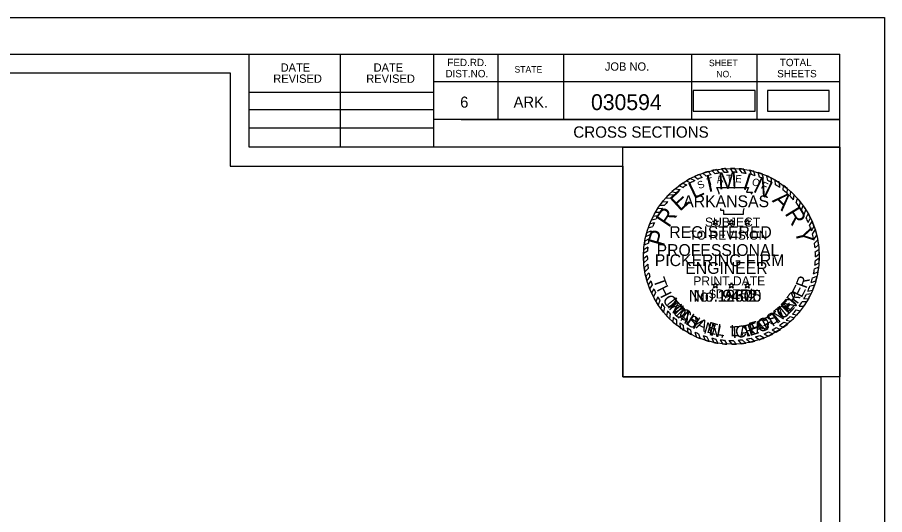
# Model space of a CAD drawing. Extents: x 1368713 to 1370673, y 380279 to 380950.
# Drawn here: x 1370223.2 to 1370315.2, y 380471.1 to 380523.8 of the extents above; entities that cross this region are included whole.
import ezdxf

# ---------------------------------------------------------------- set-up
doc = ezdxf.new("R2010")
doc.units = 0
for name, color, linetype in [('R_Border', 7, 'Continuous'), ('R_Border Notes', 7, 'Continuous'), ('R_No Plot', 7, 'Continuous'), ('R_Water', 7, 'Continuous'), ('STAMP_PE_CRAFTON', 7, 'Continuous'), ('STAMP_PE_FOSTER', 7, 'Continuous'), ('STAMP_PE_SEAL-INFO', 7, 'Continuous'), ('STAMP_PE_TAEGTMEYER', 7, 'Continuous'), ('STAMP_PE_TXT', 7, 'Continuous'), ('STAMP_PRELIMINARY', 7, 'Continuous')]:
    doc.layers.add(name, color=color, linetype=linetype)

msp = doc.modelspace()

# ---------------------------------------------------------------- linework, layer by layer
at = {"layer": 'R_Border'}
for p, q in [((1369994.283, 380519.876), (1370310.463, 380519.876)), ((1370247.823, 380509.996), (1370247.823, 380519.876)), ((1370257.503, 380509.996), (1370257.503, 380519.876)), ((1370267.363, 380519.876), (1370267.363, 380509.996)), ((1370274.203, 380519.876), (1370274.203, 380512.936)), ((1370281.143, 380519.876), (1370281.143, 380512.936)), ((1370294.723, 380519.876), (1370294.723, 380512.936)), ((1370301.663, 380519.876), (1370301.663, 380512.936)), ((1370310.463, 380314.416), (1370310.463, 380519.876)), ((1370310.463, 380516.936), (1370267.363, 380516.936)), ((1370310.463, 380516.956), (1370310.463, 380516.956)), ((1370247.823, 380515.856), (1370267.363, 380515.856)), ((1370247.823, 380513.996), (1370267.363, 380513.996)), ((1370310.463, 380512.936), (1370267.363, 380512.936)), ((1370270.323, 380512.936), (1370310.463, 380512.936)), ((1370247.823, 380512.056), (1370267.363, 380512.056)), ((1370310.463, 380509.996), (1370247.823, 380509.996))]:
    msp.add_line(p, q, dxfattribs=at)
at = {"layer": 'R_No Plot'}
for points in [[(1369981.875, 380523.77), (1370315.215, 380523.77), (1370315.215, 380310.433), (1369981.875, 380310.433)], [(1370308.463, 380419.146), (1369996.283, 380419.146), (1369996.283, 380517.876), (1370245.823, 380517.876), (1370245.823, 380507.996), (1370263.363, 380507.996), (1370287.463, 380507.996), (1370287.463, 380485.663), (1370308.463, 380485.663)], [(1369996.283, 380517.876), (1370245.823, 380517.876), (1370245.823, 380507.996), (1370263.363, 380507.996), (1370287.463, 380507.996), (1370287.463, 380485.663), (1370308.463, 380485.663), (1370308.463, 380316.416), (1369996.283, 380316.416)], [(1370287.463, 380509.996), (1370310.463, 380509.996), (1370310.463, 380485.663), (1370287.463, 380485.663)]]:
    msp.add_lwpolyline(points, close=True, dxfattribs=at)
at = {"layer": 'R_Water'}
for points in [[(1370294.911, 380513.843), (1370301.474, 380513.843), (1370301.474, 380516.029), (1370294.911, 380516.029)], [(1370302.781, 380513.843), (1370309.344, 380513.843), (1370309.344, 380516.029), (1370302.781, 380516.029)]]:
    msp.add_lwpolyline(points, close=True, dxfattribs=at)
at = {"layer": 'STAMP_PE_SEAL-INFO'}
for p, q in [((1370295.922, 380507.251), (1370296.303, 380506.946)), ((1370296.513, 380507.433), (1370296.801, 380507.086)), ((1370296.901, 380507.53), (1370297.257, 380507.187)), ((1370297.383, 380507.626), (1370297.682, 380507.259)), ((1370297.899, 380507.7), (1370298.18, 380507.317)), ((1370298.634, 380507.346), (1370298.322, 380507.739)), ((1370299.132, 380507.35), (1370298.854, 380507.76)), ((1370299.59, 380507.33), (1370299.332, 380507.754)), ((1370300.096, 380507.279), (1370299.804, 380507.723)), ((1370300.522, 380507.214), (1370300.264, 380507.67)), ((1370301.084, 380507.096), (1370300.91, 380507.555)), ((1370301.486, 380506.987), (1370301.326, 380507.456)), ((1370301.937, 380506.841), (1370301.796, 380507.32)), ((1370302.356, 380506.681), (1370302.211, 380507.177)), ((1370294.188, 380506.445), (1370294.62, 380506.222)), ((1370294.636, 380506.696), (1370295.099, 380506.471)), ((1370295.067, 380506.908), (1370295.456, 380506.633)), ((1370295.574, 380507.123), (1370295.869, 380506.798)), ((1370302.817, 380506.475), (1370302.714, 380506.973)), ((1370303.263, 380506.246), (1370303.176, 380506.755)), ((1370303.65, 380506.019), (1370303.611, 380506.52)), ((1370304.085, 380505.733), (1370304.054, 380506.248)), ((1370292.66, 380505.307), (1370293.119, 380505.169)), ((1370293.004, 380505.608), (1370293.533, 380505.507)), ((1370293.38, 380505.935), (1370293.836, 380505.73)), ((1370293.801, 380506.201), (1370294.243, 380505.999)), ((1370297.436, 380505.73), (1370300.78, 380505.73)), ((1370297.557, 380505.422), (1370297.436, 380505.73)), ((1370297.661, 380505.124), (1370297.557, 380505.422)), ((1370300.78, 380505.73), (1370300.555, 380505.238)), ((1370304.446, 380505.466), (1370304.48, 380505.953)), ((1370304.892, 380505.094), (1370304.912, 380505.616)), ((1370305.205, 380504.801), (1370305.274, 380505.3)), ((1370292.002, 380504.64), (1370292.523, 380504.601)), ((1370292.324, 380504.984), (1370292.869, 380504.943)), ((1370297.668, 380505.01), (1370297.661, 380505.124)), ((1370300.555, 380505.238), (1370301.187, 380505.238)), ((1370301.187, 380505.238), (1370301.042, 380505.01)), ((1370305.564, 380504.428), (1370305.63, 380504.954)), ((1370305.837, 380504.112), (1370305.974, 380504.583)), ((1370291.143, 380503.515), (1370291.659, 380503.548)), ((1370291.378, 380503.859), (1370291.883, 380503.854)), ((1370291.656, 380504.228), (1370292.205, 380504.251)), ((1370297.859, 380503.301), (1370297.833, 380503.519)), ((1370300.297, 380503.519), (1370300.219, 380503.209)), ((1370306.161, 380503.694), (1370306.297, 380504.194)), ((1370306.381, 380503.379), (1370306.559, 380503.843)), ((1370290.666, 380502.69), (1370291.164, 380502.755)), ((1370290.897, 380503.114), (1370291.386, 380503.134)), ((1370298.174, 380503.301), (1370297.859, 380503.301)), ((1370298.174, 380502.871), (1370298.174, 380503.301)), ((1370300.203, 380502.871), (1370298.174, 380502.871)), ((1370300.219, 380503.209), (1370300.203, 380502.871)), ((1370306.689, 380502.882), (1370306.872, 380503.373)), ((1370306.889, 380502.515), (1370307.115, 380502.96)), ((1370290.294, 380501.869), (1370290.798, 380502.015)), ((1370290.478, 380502.301), (1370290.981, 380502.405)), ((1370307.12, 380502.031), (1370307.346, 380502.516)), ((1370307.26, 380501.694), (1370307.524, 380502.128)), ((1370307.455, 380501.145), (1370307.726, 380501.62)), ((1370289.883, 380500.552), (1370290.353, 380500.745)), ((1370289.987, 380500.96), (1370290.465, 380501.128)), ((1370290.144, 380501.463), (1370290.628, 380501.599)), ((1370307.563, 380500.781), (1370307.857, 380501.233)), ((1370290.161, 380499.847), (1370289.716, 380499.625)), ((1370290.247, 380500.306), (1370289.782, 380500.057)), ((1370307.696, 380500.222), (1370308.015, 380500.669)), ((1370307.765, 380499.842), (1370308.118, 380500.195)), ((1370290.066, 380498.986), (1370289.645, 380498.73)), ((1370290.102, 380499.412), (1370289.666, 380499.131)), ((1370307.831, 380499.333), (1370308.204, 380499.669)), ((1370307.863, 380498.915), (1370308.254, 380499.206)), ((1370290.049, 380498.493), (1370289.644, 380498.158)), ((1370290.056, 380498.086), (1370289.665, 380497.761)), ((1370307.865, 380497.991), (1370308.284, 380498.268)), ((1370307.876, 380498.397), (1370308.281, 380498.718)), ((1370290.089, 380497.591), (1370289.718, 380497.234)), ((1370290.141, 380497.162), (1370289.787, 380496.788)), ((1370307.775, 380497.097), (1370308.218, 380497.316)), ((1370307.825, 380497.485), (1370308.259, 380497.742)), ((1370290.22, 380496.703), (1370289.88, 380496.335)), ((1370290.313, 380496.284), (1370290.001, 380495.869)), ((1370307.576, 380496.145), (1370308.048, 380496.347)), ((1370307.684, 380496.597), (1370308.139, 380496.792)), ((1370290.437, 380495.837), (1370290.142, 380495.419)), ((1370290.578, 380495.414), (1370290.296, 380495.002)), ((1370307.294, 380495.271), (1370307.777, 380495.402)), ((1370307.429, 380495.651), (1370307.919, 380495.852)), ((1370290.744, 380494.987), (1370290.483, 380494.565)), ((1370290.916, 380494.604), (1370290.688, 380494.143)), ((1370306.919, 380494.42), (1370307.407, 380494.488)), ((1370307.08, 380494.757), (1370307.568, 380494.853)), ((1370291.151, 380494.146), (1370290.96, 380493.656)), ((1370291.387, 380493.742), (1370291.203, 380493.271)), ((1370291.589, 380493.43), (1370291.479, 380492.878)), ((1370306.475, 380493.641), (1370306.953, 380493.635)), ((1370306.647, 380493.922), (1370307.148, 380493.976)), ((1370291.87, 380493.04), (1370291.768, 380492.509)), ((1370292.174, 380492.662), (1370292.087, 380492.142)), ((1370305.828, 380492.753), (1370306.289, 380492.674)), ((1370306.136, 380493.147), (1370306.64, 380493.15)), ((1370292.476, 380492.325), (1370292.414, 380491.802)), ((1370292.799, 380491.999), (1370292.769, 380491.47)), ((1370293.143, 380491.687), (1370293.14, 380491.158)), ((1370304.784, 380491.688), (1370305.255, 380491.559)), ((1370305.19, 380492.061), (1370305.631, 380491.923)), ((1370305.445, 380492.32), (1370305.922, 380492.235)), ((1370293.503, 380491.392), (1370293.522, 380490.868)), ((1370293.842, 380491.143), (1370293.878, 380490.624)), ((1370294.269, 380490.861), (1370294.329, 380490.348)), ((1370294.619, 380490.655), (1370294.71, 380490.142)), ((1370303.294, 380490.648), (1370303.711, 380490.416)), ((1370303.709, 380490.893), (1370304.158, 380490.698)), ((1370304.053, 380491.121), (1370304.491, 380490.932)), ((1370304.513, 380491.464), (1370304.981, 380491.318)), ((1370295.1, 380490.405), (1370295.257, 380489.884)), ((1370295.473, 380490.236), (1370295.645, 380489.726)), ((1370295.965, 380490.044), (1370296.174, 380489.542)), ((1370296.375, 380489.909), (1370296.601, 380489.42)), ((1370296.883, 380489.771), (1370297.095, 380489.305)), ((1370297.28, 380489.685), (1370297.527, 380489.227)), ((1370300.563, 380489.67), (1370300.952, 380489.33)), ((1370301.056, 380489.774), (1370301.434, 380489.449)), ((1370301.515, 380489.898), (1370301.932, 380489.601)), ((1370302.008, 380490.061), (1370302.451, 380489.793)), ((1370302.427, 380490.226), (1370302.851, 380489.965)), ((1370302.887, 380490.435), (1370303.37, 380490.223)), ((1370297.78, 380489.603), (1370298.02, 380489.163)), ((1370298.217, 380489.556), (1370298.491, 380489.127)), ((1370298.702, 380489.529), (1370299.004, 380489.116)), ((1370299.161, 380489.527), (1370299.505, 380489.131)), ((1370299.68, 380489.554), (1370300.006, 380489.174)), ((1370300.118, 380489.6), (1370300.491, 380489.242))]:
    msp.add_line(p, q, dxfattribs=at)
for radius, start, end in [(9.323, 105.23389, 109.03519), (9.323, 99.75254, 102.77648), (8.914, 98.25799, 101.03289), (9.323, 93.93815, 96.55172), (8.914, 92.11016, 95.03666), (9.323, 87.72979, 90.67067), (8.914, 85.96279, 88.9097), (9.323, 81.97315, 84.82355), (8.914, 79.92642, 82.69597), (9.323, 75.31251, 77.94263), (9.323, 69.60611, 72.30577), (9.323, 117.65441, 120.80988), (8.914, 115.68692, 119.15827), (9.323, 111.31242, 114.70259), (8.914, 110.30864, 113.16588), (8.914, 104.03521, 107.36155), (8.914, 73.55748, 76.23144), (8.914, 67.62483, 70.50398), (9.323, 63.13288, 66.2704), (8.914, 61.15575, 64.37837), (9.323, 56.90029, 60.09423), (9.323, 129.73259, 132.53764), (8.914, 127.52969, 130.96829), (9.323, 123.61993, 126.59063), (8.914, 121.97456, 125.11001), (8.914, 54.92383, 58.27016), (8.914, 48.30163, 52.03953), (9.323, 50.3492, 53.71593), (9.323, 44.3405, 47.39292), (9.323, 135.40208, 138.30314), (8.914, 133.13306, 136.25623), (8.914, 42.22116, 45.55119), (9.323, 38.12472, 41.23157), (9.323, 147.00719, 149.89904), (9.323, 141.60556, 144.44865), (8.914, 145.01972, 148.21036), (8.914, 139.30101, 142.58729), (8.914, 36.13503, 39.53106), (9.323, 31.96138, 35.42937), (9.323, 152.86398, 155.51889), (8.914, 151.03153, 153.57304), (8.914, 29.90321, 33.66454), (9.323, 25.93909, 29.01247), (9.323, 158.40766, 161.07015), (8.914, 156.34018, 159.23194), (8.914, 23.77322, 27.22114), (8.914, 17.68022, 21.42509), (9.323, 19.95381, 23.31409), (9.323, 164.3068, 166.89395), (8.914, 162.43309, 165.00133), (8.914, 11.54445, 15.23639), (9.323, 13.84205, 17.44468), (9.323, 170.0003, 172.68778), (8.914, 167.90481, 170.90393), (8.914, 5.7599, 9.06056), (9.323, 7.58519, 10.86211), (9.323, 175.74093, 178.2066), (8.914, 173.73, 176.47337), (8.914, 359.73289, 3.06392), (9.323, 1.72155, 4.72681), (9.323, 181.72508, 184.16255), (8.914, 179.64537, 182.26333), (8.914, 353.86319, 357.12742), (9.323, 355.71562, 358.95694), (9.323, 187.42037, 190.19271), (8.914, 185.45389, 188.23401), (8.914, 348.07782, 351.34355), (9.323, 349.83047, 353.08845), (9.323, 193.03695, 195.99732), (8.914, 191.22736, 193.98583), (8.914, 341.77699, 345.09248), (9.323, 343.89247, 347.03502), (9.323, 198.89671, 201.62812), (8.914, 196.96751, 199.83526), (8.914, 335.6038, 339.18578), (9.323, 337.38367, 340.99332), (9.323, 204.54793, 207.43282), (8.914, 202.77613, 205.47915), (8.914, 329.55488, 333.20757), (9.323, 331.40371, 334.93315), (9.323, 210.86355, 213.65709), (8.914, 208.78826, 211.79343), (8.914, 214.18375, 217.27474), (8.914, 323.58513, 327.44069), (9.323, 325.44052, 328.98725), (9.323, 216.61154, 219.49098), (8.914, 220.39088, 223.30564), (8.914, 316.65308, 320.37109), (9.323, 318.28455, 321.80429), (9.323, 222.47995, 225.38008), (8.914, 226.24938, 229.24068), (8.914, 310.77436, 314.31605), (9.323, 312.45177, 315.66328), (9.323, 228.36648, 231.34802), (8.914, 232.22904, 234.93361), (9.323, 234.29502, 236.94517), (8.914, 238.22227, 240.83529), (8.914, 299.07679, 302.17235), (9.323, 300.62101, 303.87026), (8.914, 304.82299, 308.51428), (9.323, 306.37206, 310.20799), (9.323, 240.1977, 242.86128), (8.914, 244.32043, 246.94859), (9.323, 246.57598, 249.15579), (8.914, 250.34912, 253.12157), (8.914, 256.50505, 259.11916), (8.914, 280.34588, 283.58137), (8.914, 286.64233, 289.97826), (9.323, 288.57086, 291.97334), (8.914, 292.87452, 296.11851), (9.323, 294.64808, 298.21662), (9.323, 252.59667, 255.32518), (9.323, 258.44328, 261.13983), (8.914, 262.37828, 265.20115), (9.323, 264.19784, 267.10092), (8.914, 268.3215, 271.27698), (9.323, 270.25484, 273.33609), (8.914, 274.61565, 277.44863), (9.323, 276.42389, 279.43574), (9.323, 282.31994, 285.37019)]:
    msp.add_arc((1370298.963, 380498.438), radius, start, end, dxfattribs=at)
at = {"layer": 'STAMP_PE_TXT'}
for p, q in [((1370297.142, 380502.01), (1370296.944, 380502.154)), ((1370296.944, 380502.154), (1370297.189, 380502.154)), ((1370297.066, 380501.776), (1370297.142, 380502.01)), ((1370297.265, 380501.921), (1370297.066, 380501.776)), ((1370297.189, 380502.154), (1370297.265, 380502.387)), ((1370297.265, 380502.387), (1370297.34, 380502.154)), ((1370297.463, 380501.776), (1370297.265, 380501.921)), ((1370297.34, 380502.154), (1370297.586, 380502.154)), ((1370297.586, 380502.154), (1370297.387, 380502.01)), ((1370297.387, 380502.01), (1370297.463, 380501.776)), ((1370298.84, 380502.01), (1370298.642, 380502.154)), ((1370298.642, 380502.154), (1370298.887, 380502.154)), ((1370298.764, 380501.776), (1370298.84, 380502.01)), ((1370298.963, 380501.921), (1370298.764, 380501.776)), ((1370298.887, 380502.154), (1370298.963, 380502.387)), ((1370298.963, 380502.387), (1370299.038, 380502.154)), ((1370299.161, 380501.776), (1370298.963, 380501.921)), ((1370299.038, 380502.154), (1370299.284, 380502.154)), ((1370299.284, 380502.154), (1370299.085, 380502.01)), ((1370299.085, 380502.01), (1370299.161, 380501.776)), ((1370300.538, 380502.01), (1370300.34, 380502.154)), ((1370300.34, 380502.154), (1370300.585, 380502.154)), ((1370300.462, 380501.776), (1370300.538, 380502.01)), ((1370300.661, 380501.921), (1370300.462, 380501.776)), ((1370300.585, 380502.154), (1370300.661, 380502.387)), ((1370300.661, 380502.387), (1370300.736, 380502.154)), ((1370300.859, 380501.776), (1370300.661, 380501.921)), ((1370300.736, 380502.154), (1370300.982, 380502.154)), ((1370300.982, 380502.154), (1370300.783, 380502.01)), ((1370300.783, 380502.01), (1370300.859, 380501.776)), ((1370297.142, 380495.303), (1370296.944, 380495.447)), ((1370296.944, 380495.447), (1370297.189, 380495.447)), ((1370297.066, 380495.069), (1370297.142, 380495.303)), ((1370297.265, 380495.214), (1370297.066, 380495.069)), ((1370297.189, 380495.447), (1370297.265, 380495.68)), ((1370297.265, 380495.68), (1370297.34, 380495.447)), ((1370297.463, 380495.069), (1370297.265, 380495.214)), ((1370297.34, 380495.447), (1370297.586, 380495.447)), ((1370297.586, 380495.447), (1370297.387, 380495.303)), ((1370297.387, 380495.303), (1370297.463, 380495.069)), ((1370298.84, 380495.303), (1370298.642, 380495.447)), ((1370298.642, 380495.447), (1370298.887, 380495.447)), ((1370298.764, 380495.069), (1370298.84, 380495.303)), ((1370298.963, 380495.214), (1370298.764, 380495.069)), ((1370298.887, 380495.447), (1370298.963, 380495.68)), ((1370298.963, 380495.68), (1370299.038, 380495.447)), ((1370299.161, 380495.069), (1370298.963, 380495.214)), ((1370299.038, 380495.447), (1370299.284, 380495.447)), ((1370299.284, 380495.447), (1370299.085, 380495.303)), ((1370299.085, 380495.303), (1370299.161, 380495.069)), ((1370300.538, 380495.303), (1370300.34, 380495.447)), ((1370300.34, 380495.447), (1370300.585, 380495.447)), ((1370300.462, 380495.069), (1370300.538, 380495.303)), ((1370300.661, 380495.214), (1370300.462, 380495.069)), ((1370300.585, 380495.447), (1370300.661, 380495.68)), ((1370300.661, 380495.68), (1370300.736, 380495.447)), ((1370300.859, 380495.069), (1370300.661, 380495.214)), ((1370300.736, 380495.447), (1370300.982, 380495.447)), ((1370300.982, 380495.447), (1370300.783, 380495.303)), ((1370300.783, 380495.303), (1370300.859, 380495.069))]:
    msp.add_line(p, q, dxfattribs=at)
at = {"layer": 'STAMP_PRELIMINARY'}
msp.add_circle((1370298.963, 380498.438), 9.323, dxfattribs=at)

# ---------------------------------------------------------------- texts
at = {"layer": 'R_Border'}
for s, height, p in [('FED.RD.', 0.7819, (1370268.843, 380518.596)), ('SHEET', 0.684, (1370296.583, 380518.596)), ('TOTAL', 0.7819, (1370304.103, 380518.596)), ('DATE', 0.8792, (1370251.16, 380518.012)), ('DATE', 0.8792, (1370261.02, 380518.012)), ('DIST.NO.', 0.7819, (1370268.643, 380517.416)), ('STATE', 0.684, (1370275.963, 380517.916)), ('JOB NO.', 0.8792, (1370285.543, 380518.116)), ('SHEETS', 0.7819, (1370303.823, 380517.416)), ('REVISED', 0.8792, (1370250.38, 380516.832)), ('REVISED', 0.8792, (1370260.24, 380516.832)), ('NO.', 0.684, (1370297.363, 380517.416)), ('6', 1.172, (1370270.203, 380514.196)), ('ARK.', 1.1723, (1370275.863, 380514.196))]:
    msp.add_text(s, height=height, rotation=360, dxfattribs=at).set_placement(p)
at = {"layer": 'R_Border Notes'}
for s, height, p in [('030594', 1.68, (1370284.074, 380513.941)), ('CROSS SECTIONS', 1.2, (1370282.201, 380511.014))]:
    msp.add_text(s, height=height, rotation=360, dxfattribs=at).set_placement(p)
at = {"layer": 'STAMP_PE_CRAFTON'}
for s, rotation, p in [('No. 12370', 360, (1370294.425, 380493.635)), ('T', 310.74416, (1370291.929, 380493.336)), ('N', 49.24107, (1370305.245, 380492.46)), ('O', 317.64216, (1370292.596, 380492.525)), ('N', 324.45371, (1370293.442, 380491.74)), ('T', 34.11362, (1370303.539, 380491.077)), ('O', 41.83906, (1370304.398, 380491.679)), ('Y', 331.16864, (1370294.475, 380491.024)), ('A', 20.51248, (1370301.643, 380490.194)), ('F', 28.78207, (1370302.624, 380490.568)), ('N', 347.47515, (1370296.529, 380490.108)), ('C', 6.01169, (1370299.434, 380489.779)), ('R', 14.81888, (1370300.53, 380489.894)), ('.', 356.89262, (1370297.759, 380489.831))]:
    msp.add_text(s, height=1.25, rotation=rotation, dxfattribs=at).set_placement(p)
at = {"layer": 'STAMP_PE_FOSTER'}
for s, height, rotation, p in [('No. 9402', 1.25, 360, (1370294.948, 380493.635)), ('R', 1.2, 54.5031, (1370305.687, 380493.249)), ('M', 1.2, 308.33902, (1370292.079, 380493.46)), ('E', 1.2, 46.96131, (1370304.963, 380492.428)), ('I', 1.2, 314.18423, (1370292.876, 380492.523)), ('C', 1.2, 319.87327, (1370293.23, 380492.169)), ('S', 1.2, 31.72336, (1370303.153, 380491.051)), ('T', 1.2, 39.41938, (1370304.105, 380491.678)), ('H', 1.2, 327.72349, (1370294.16, 380491.433)), ('A', 1.2, 335.72761, (1370295.14, 380490.851)), ('F', 1.2, 15.86908, (1370300.998, 380490.193)), ('O', 1.2, 23.71897, (1370302.042, 380490.521)), ('E', 1.2, 343.5779, (1370296.278, 380490.381)), ('L', 1.2, 350.81148, (1370297.337, 380490.103)), ('L', 1.2, 1.26658, (1370298.876, 380489.947)), ('.', 1.2, 6.80354, (1370299.923, 380490.005))]:
    msp.add_text(s, height=height, rotation=rotation, dxfattribs=at).set_placement(p)
at = {"layer": 'STAMP_PE_TAEGTMEYER'}
for s, rotation, p in [('T', 289.64597, (1370290.657, 380495.948)), ('R', 69.57001, (1370306.908, 380494.953)), ('H', 296.73386, (1370291.017, 380494.964)), ('E', 63.0984, (1370306.409, 380493.971)), ('O', 303.77078, (1370291.61, 380493.856)), ('No. 19605', 360, (1370294.425, 380493.635)), ('Y', 53.99864, (1370305.74, 380493.031)), ('M', 314.20329, (1370292.265, 380492.905)), ('E', 46.80938, (1370305.001, 380492.216)), ('A', 321.0594, (1370293.226, 380491.94)), ('M', 39.30005, (1370303.961, 380491.336)), ('S', 327.82385, (1370294.053, 380491.296)), ('G', 23.30524, (1370301.962, 380490.3)), ('T', 31.46601, (1370303.063, 380490.793)), ('N', 344.27273, (1370295.949, 380490.29)), ('T', 3.00609, (1370298.827, 380489.759)), ('A', 8.98261, (1370299.874, 380489.814)), ('E', 17.68363, (1370300.913, 380489.97)), ('.', 350.64643, (1370297.162, 380489.958))]:
    msp.add_text(s, height=1.25, rotation=rotation, dxfattribs=at).set_placement(p)
at = {"layer": 'STAMP_PE_TXT'}
for s, height, rotation, p in [('S', 0.781, 23.5541, (1370295.561, 380505.542)), ('T', 0.781, 16.311, (1370296.484, 380505.914)), ('A', 0.781, 9.0679, (1370297.447, 380506.167)), ('T', 0.781, 1.82479, (1370298.433, 380506.296)), ('E', 0.781, 355.20019, (1370299.343, 380506.305)), ('O', 0.781, 342.25065, (1370301.07, 380506.028)), ('F', 0.781, 335.00755, (1370302.035, 380505.69)), ('ARKANSAS', 1.25, 360, (1370293.855, 380503.649)), ('REGISTERED', 1.25, 360, (1370292.379, 380500.379)), ('PROFESSIONAL', 1.25, 360, (1370291.031, 380498.478)), ('ENGINEER', 1.25, 360, (1370294.072, 380496.576))]:
    msp.add_text(s, height=height, rotation=rotation, dxfattribs=at).set_placement(p)
at = {"layer": 'STAMP_PRELIMINARY'}
for s, height, rotation, p in [('M', 1.8, 3.10738, (1370297.598, 380505.534)), ('I', 1.8, 342.31637, (1370300.066, 380505.601)), ('L', 1.8, 25.51305, (1370294.971, 380504.466)), ('I', 1.8, 12.52485, (1370296.5, 380505.225)), ('N', 1.8, 333.9382, (1370301.174, 380505.327)), ('E', 1.8, 42.35784, (1370293.489, 380503.135)), ('A', 1.8, 315.65789, (1370303.207, 380504.302)), ('R', 1.8, 56.22922, (1370292.333, 380501.402)), ('R', 1.8, 301.38306, (1370304.575, 380502.988)), ('SUBJECT', 0.96, 360, (1370296.163, 380501.588)), ('P', 1.8, 73.91301, (1370291.784, 380499.379)), ('TO REVISION', 0.96, 360, (1370294.498, 380500.203)), ('Y', 1.8, 283.25926, (1370305.665, 380501.201)), ('PICKERING FIRM', 1.25, 360, (1370290.836, 380497.401)), ('PRINT DATE', 0.96, 360, (1370294.92, 380495.354)), ('$DATE$', 0.96, 360, (1370296.597, 380493.969))]:
    msp.add_text(s, height=height, rotation=rotation, dxfattribs=at).set_placement(p)

doc.saveas('drawing.dxf')
